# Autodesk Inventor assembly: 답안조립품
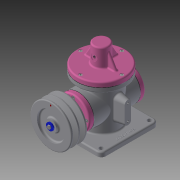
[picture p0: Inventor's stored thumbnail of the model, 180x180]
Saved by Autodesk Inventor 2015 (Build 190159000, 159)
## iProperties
Created: 2020-02
Part Number: 답안조립품
Document SubType Name: Assembly
Designer: LINEART-A501-2
Mass: 2562.92 g
Surface Area: 2485.6 cm^2
Volume: 789.842 cm^3
Density: 3.24485 g/cm^3
Author: LINEART-A501-2
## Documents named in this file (21)
- C:\Users\LINEART-A501-2\Desktop\600206V1029\답안조립품.iam
- C:\Users\LINEART-A501-2\Desktop\600206V1029\본체.ipt
- C:\Users\LINEART-A501-2\Desktop\600206V1029\뒤커버.ipt
- C:\Users\LINEART-A501-2\Desktop\600206V1029\개스킷 A.ipt
- C:\Users\LINEART-A501-2\Desktop\600206V1029\베어링 17 x 40 x 12.ipt
- C:\Users\LINEART-A501-2\Desktop\600206V1029\편심축.ipt
- C:\Users\LINEART-A501-2\Desktop\600206V1029\키 4 x 4 x 25.ipt
- C:\Users\LINEART-A501-2\Desktop\600206V1029\앞커버.ipt
- C:\Users\LINEART-A501-2\Desktop\600206V1029\오일 실 17 30 8.ipt
- C:\Users\LINEART-A501-2\Desktop\600206V1029\육각 소켓 머리 볼트 M4 x 10.ipt
- C:\Users\LINEART-A501-2\Desktop\600206V1029\V-벨트풀리.ipt
- C:\Users\LINEART-A501-2\Desktop\600206V1029\와셔 4x16.ipt
- C:\Users\LINEART-A501-2\Desktop\600206V1029\볼트 M4 x 10.ipt
- C:\Users\LINEART-A501-2\Desktop\600206V1029\링크.ipt
- C:\Users\LINEART-A501-2\Desktop\600206V1029\클레비스 핀 6 x 22.ipt
- 클레비스 핀 6 x 22.ipt
- C:\Users\LINEART-A501-2\Desktop\600206V1029\E-링.ipt
- C:\Users\LINEART-A501-2\Desktop\600206V1029\슬라이더.ipt
- C:\Users\LINEART-A501-2\Desktop\600206V1029\개스킷 B.ipt
- C:\Users\LINEART-A501-2\Desktop\600206V1029\덮개.ipt
- C:\Users\LINEART-A501-2\Desktop\600206V1029\가변스프링.ipt
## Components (6 placed, 5 different names)
1. 개스킷 A:1
2. 개스킷 A:2
3. V-벨트풀리:1 — 각도:3
4. E-링:1 — 각도:5
5. 개스킷 B:1
6. 가변스프링:1
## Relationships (2: Angle 2)
- 각도:3 [Angle]: V-벨트풀리:1
- 각도:5 [Angle]: E-링:1
